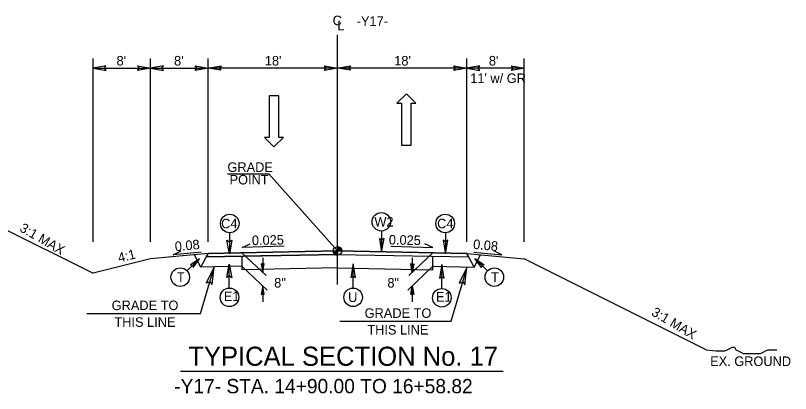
# Model space of a CAD drawing. Extents: x 2320980 to 2456309, y 595047 to 606177.
# Drawn here: x 2456201 to 2456308.8, y 595786.4 to 595839 of the extents above; entities that cross this region are included whole.
import ezdxf

# ---------------------------------------------------------------- set-up
doc = ezdxf.new("R2010")
doc.units = 0
for name, color, linetype in [('Old_Level_1', 7, 'Continuous'), ('Old_Level_11', 7, 'Continuous'), ('Old_Level_2', 7, 'Continuous'), ('Old_Level_20', 7, 'Continuous'), ('Old_Level_21', 7, 'Continuous'), ('Old_Level_3', 7, 'Continuous'), ('Prop Dimension', 7, 'Continuous'), ('Prop Dimension Text', 7, 'Continuous'), ('Prop Lane Arrow CELL', 7, 'Continuous'), ('Prop Terminator CELL', 7, 'Continuous'), ('Typical Grade Point Symbol CELL', 7, 'Continuous'), ('Typical ID Circle CELL', 7, 'Continuous'), ('Typical Pavement Slope CELL', 7, 'Continuous'), ('Typical Pavement Slope Information CELL', 7, 'Continuous'), ('Typical Slope Point Local CELL', 7, 'Continuous'), ('Typical Terminator CELL', 7, 'Continuous')]:
    doc.layers.add(name, color=color, linetype=linetype)

msp = doc.modelspace()

# ---------------------------------------------------------------- linework, layer by layer
at = {"layer": 'Old_Level_1'}
for p, q in [((2456230.5, 595816.96), (2456236.26, 595816.96)), ((2456245.81, 595806.23), (2456236.26, 595816.96)), ((2456227.81, 595805.87), (2456219.81, 595805.12)), ((2456263.81, 595805.87), (2456271.81, 595805.12)), ((2456232.54, 595803.61), (2456232.54, 595805.49)), ((2456259.09, 595803.62), (2456259.09, 595805.49)), ((2456232.54, 595804.09), (2456226.82, 595803.97)), ((2456245.81, 595803.88), (2456232.54, 595803.61)), ((2456245.81, 595803.88), (2456259.09, 595803.62)), ((2456259.09, 595804.09), (2456264.81, 595803.97))]:
    msp.add_line(p, q, dxfattribs=at)
at = {"layer": 'Old_Level_11'}
for points in [[(2456228.36, 595801.55), (2456228.64, 595803.96), (2456227.56, 595801.77), (2456228.05, 595801.94)], [(2456263.55, 595801.51), (2456263.83, 595803.93), (2456262.75, 595801.74), (2456263.24, 595801.91)]]:
    msp.add_lwpolyline(points, close=True, dxfattribs=at)
at = {"layer": 'Old_Level_21'}
for p, q in [((2456211.81, 595807.52), (2456211.81, 595833.02)), ((2456219.81, 595807.52), (2456219.81, 595833.02)), ((2456227.81, 595807.52), (2456227.81, 595833.02)), ((2456263.81, 595807.52), (2456263.81, 595833.02)), ((2456271.81, 595807.52), (2456271.81, 595833.02)), ((2456211.81, 595831.69), (2456219.81, 595831.69)), ((2456219.81, 595831.69), (2456227.81, 595831.69)), ((2456245.81, 595831.69), (2456227.81, 595831.69)), ((2456263.81, 595831.69), (2456245.81, 595831.69)), ((2456271.81, 595831.69), (2456263.81, 595831.69)), ((2456226.76, 595797.52), (2456228.65, 595803.99)), ((2456261.65, 595796.45), (2456263.84, 595803.96)), ((2456210.95, 595797.52), (2456226.76, 595797.52)), ((2456246.14, 595796.45), (2456261.65, 595796.45))]:
    msp.add_line(p, q, dxfattribs=at)
at = {"layer": 'Old_Level_3'}
for p, q in [((2456245.81, 595805.75), (2456227.81, 595805.39)), ((2456223.96, 595789.51), (2456268.88, 595789.51))]:
    msp.add_line(p, q, dxfattribs=at)
at = {"layer": 'Prop Dimension'}
for p, q in [((2456232.53, 595805.97), (2456235.91, 595802.79)), ((2456259.1, 595805.97), (2456255.72, 595802.79)), ((2456235.41, 595805.26), (2456235.41, 595803.26)), ((2456256.22, 595805.26), (2456256.22, 595803.26)), ((2456232.53, 595804.09), (2456236.03, 595800.79)), ((2456259.1, 595804.09), (2456255.6, 595800.79)), ((2456235.41, 595801.38), (2456235.41, 595799.13)), ((2456256.22, 595801.38), (2456256.22, 595799.13))]:
    msp.add_line(p, q, dxfattribs=at)
at = {"layer": 'Prop Dimension Text'}
for p, q in [((2456245.81, 595820.05), (2456245.81, 595836.31)), ((2456245.81, 595801.54), (2456245.81, 595820.05)), ((2456224.88, 595803.47), (2456226.64, 595805.15)), ((2456266.69, 595803.47), (2456264.93, 595805.16))]:
    msp.add_line(p, q, dxfattribs=at)
for points in [[(2456238.39, 595806.88), (2456232.54, 595806.72), (2456233.67, 595807.21)], [(2456253.24, 595806.88), (2456259.09, 595806.72), (2456257.96, 595807.21)], [(2456226.85, 595806.05), (2456222.96, 595805.67), (2456224.06, 595806.24)], [(2456264.78, 595806.05), (2456268.67, 595805.67), (2456267.57, 595806.24)]]:
    msp.add_lwpolyline(points, dxfattribs=at)
for centre in [(2456230.83, 595810.05), (2456251.91, 595810.29), (2456260.8, 595810.05), (2456223.94, 595802.58), (2456267.63, 595802.58), (2456230.79, 595799.77), (2456247.99, 595799.78), (2456260.33, 595799.71)]:
    msp.add_circle(centre, 1.29, dxfattribs=at)
at = {"layer": 'Prop Lane Arrow CELL'}
for p, q in [((2456236.3, 595827.84), (2456236.3, 595822.02)), ((2456237.67, 595827.84), (2456236.3, 595827.84)), ((2456237.67, 595822.02), (2456237.67, 595827.84)), ((2456255.42, 595828.1), (2456254.09, 595826.79)), ((2456256.71, 595826.79), (2456255.42, 595828.1)), ((2456254.09, 595826.79), (2456254.71, 595826.79)), ((2456254.71, 595826.79), (2456254.71, 595820.97)), ((2456256.09, 595820.97), (2456256.09, 595826.79)), ((2456256.09, 595826.79), (2456256.71, 595826.79)), ((2456236.3, 595822.02), (2456235.67, 595822.02)), ((2456235.67, 595822.02), (2456236.96, 595820.71)), ((2456236.96, 595820.71), (2456238.29, 595822.02)), ((2456238.29, 595822.02), (2456237.67, 595822.02)), ((2456254.71, 595820.97), (2456256.09, 595820.97))]:
    msp.add_line(p, q, dxfattribs=at)
at = {"layer": 'Prop Terminator CELL'}
for points in [[(2456235.2, 595804.45), (2456235.41, 595803.26), (2456235.62, 595804.46), (2456235.41, 595804.31)], [(2456256.43, 595804.45), (2456256.22, 595803.26), (2456256.01, 595804.46), (2456256.22, 595804.31)], [(2456235.61, 595800.18), (2456235.41, 595801.38), (2456235.19, 595800.18), (2456235.41, 595800.33)], [(2456256.02, 595800.18), (2456256.22, 595801.38), (2456256.44, 595800.18), (2456256.22, 595800.33)]]:
    msp.add_lwpolyline(points, close=True, dxfattribs=at)
at = {"layer": 'Typical Grade Point Symbol CELL'}
for p, q in [((2456245.81, 595806.23), (2456245.81, 595806.83)), ((2456245.22, 595806.23), (2456245.81, 595806.23)), ((2456246.41, 595806.23), (2456245.81, 595806.23)), ((2456245.81, 595805.64), (2456245.81, 595806.23)), ((2456245.81, 595806.23), (2456245.81, 595805.64))]:
    msp.add_line(p, q, dxfattribs=at)
for points in [[(2456245.82, 595806.83), (2456245.82, 595806.83), (2456245.82, 595806.23)], [(2456245.83, 595806.83), (2456245.83, 595806.23)], [(2456245.84, 595806.83), (2456245.84, 595806.23)], [(2456245.85, 595806.83), (2456245.85, 595806.23)], [(2456245.87, 595806.83), (2456245.87, 595806.23)], [(2456245.88, 595806.83), (2456245.88, 595806.23)], [(2456245.89, 595806.82), (2456245.89, 595806.23)], [(2456245.9, 595806.82), (2456245.9, 595806.23)], [(2456245.91, 595806.82), (2456245.91, 595806.23)], [(2456245.93, 595806.82), (2456245.93, 595806.23)], [(2456245.94, 595806.82), (2456245.94, 595806.23)], [(2456245.95, 595806.81), (2456245.95, 595806.23)], [(2456245.96, 595806.81), (2456245.96, 595806.23)], [(2456245.97, 595806.81), (2456245.97, 595806.23)], [(2456245.99, 595806.8), (2456245.99, 595806.23)], [(2456246, 595806.8), (2456246, 595806.23)], [(2456246.01, 595806.8), (2456246.01, 595806.23)], [(2456246.02, 595806.79), (2456246.02, 595806.23)], [(2456246.03, 595806.79), (2456246.03, 595806.23)], [(2456246.04, 595806.78), (2456246.04, 595806.23)], [(2456246.06, 595806.78), (2456246.06, 595806.23)], [(2456246.07, 595806.77), (2456246.07, 595806.23)], [(2456246.08, 595806.77), (2456246.08, 595806.23)], [(2456246.09, 595806.76), (2456246.09, 595806.23)], [(2456246.1, 595806.75), (2456246.1, 595806.23)], [(2456245.22, 595806.23), (2456245.22, 595806.17)], [(2456245.23, 595806.23), (2456245.23, 595806.1)], [(2456245.24, 595806.23), (2456245.24, 595806.06)], [(2456245.26, 595806.23), (2456245.26, 595806.02)], [(2456245.27, 595806.23), (2456245.27, 595805.99)], [(2456245.28, 595806.23), (2456245.28, 595805.97)], [(2456245.29, 595806.23), (2456245.29, 595805.95)], [(2456245.3, 595806.23), (2456245.3, 595805.92)], [(2456245.32, 595806.23), (2456245.32, 595805.91)], [(2456245.33, 595806.23), (2456245.33, 595805.89)], [(2456245.34, 595806.23), (2456245.34, 595805.87)], [(2456245.35, 595806.23), (2456245.35, 595805.86)], [(2456245.36, 595806.23), (2456245.36, 595805.84)], [(2456245.38, 595806.23), (2456245.38, 595805.83)], [(2456245.39, 595806.23), (2456245.39, 595805.82)], [(2456245.4, 595806.23), (2456245.4, 595805.81)], [(2456245.41, 595806.23), (2456245.41, 595805.79)], [(2456245.42, 595806.23), (2456245.42, 595805.78)], [(2456245.44, 595806.23), (2456245.44, 595805.77)], [(2456245.45, 595806.23), (2456245.45, 595805.76)], [(2456245.46, 595806.23), (2456245.46, 595805.75)], [(2456245.47, 595806.23), (2456245.47, 595805.75)], [(2456245.48, 595806.23), (2456245.48, 595805.74)], [(2456245.49, 595806.23), (2456245.49, 595805.73)], [(2456245.51, 595806.23), (2456245.51, 595805.72)], [(2456245.52, 595806.23), (2456245.52, 595805.72)], [(2456245.53, 595806.23), (2456245.53, 595805.71)], [(2456245.54, 595806.23), (2456245.54, 595805.7)], [(2456245.55, 595806.23), (2456245.55, 595805.7)], [(2456245.57, 595806.23), (2456245.57, 595805.69)], [(2456245.58, 595806.23), (2456245.58, 595805.69)], [(2456245.59, 595806.23), (2456245.59, 595805.68)], [(2456245.6, 595806.23), (2456245.6, 595805.68)], [(2456245.61, 595806.23), (2456245.61, 595805.67)], [(2456245.63, 595806.23), (2456245.63, 595805.67)], [(2456245.64, 595806.23), (2456245.64, 595805.66)], [(2456245.65, 595806.23), (2456245.65, 595805.66)], [(2456245.66, 595806.23), (2456245.66, 595805.66)], [(2456245.67, 595806.23), (2456245.67, 595805.66)], [(2456245.69, 595806.23), (2456245.69, 595805.65)], [(2456245.7, 595806.23), (2456245.7, 595805.65)], [(2456245.71, 595806.23), (2456245.71, 595805.65)], [(2456245.72, 595806.23), (2456245.72, 595805.65)], [(2456245.73, 595806.23), (2456245.73, 595805.64)], [(2456245.74, 595806.23), (2456245.74, 595805.64)], [(2456245.76, 595806.23), (2456245.76, 595805.64)], [(2456245.77, 595806.23), (2456245.77, 595805.64)], [(2456245.78, 595806.23), (2456245.78, 595805.64)], [(2456245.79, 595806.23), (2456245.79, 595805.64)], [(2456245.8, 595806.23), (2456245.8, 595805.64), (2456245.8, 595805.64)], [(2456246.12, 595806.75), (2456246.12, 595806.23)], [(2456246.13, 595806.74), (2456246.13, 595806.23)], [(2456246.14, 595806.73), (2456246.14, 595806.23)], [(2456246.15, 595806.72), (2456246.15, 595806.23)], [(2456246.16, 595806.71), (2456246.16, 595806.23)], [(2456246.18, 595806.71), (2456246.18, 595806.23)], [(2456246.19, 595806.7), (2456246.19, 595806.23)], [(2456246.2, 595806.69), (2456246.2, 595806.23)], [(2456246.21, 595806.68), (2456246.21, 595806.23)], [(2456246.22, 595806.66), (2456246.22, 595806.23)], [(2456246.24, 595806.65), (2456246.24, 595806.23)], [(2456246.25, 595806.64), (2456246.25, 595806.23)], [(2456246.26, 595806.63), (2456246.26, 595806.23)], [(2456246.27, 595806.61), (2456246.27, 595806.23)], [(2456246.28, 595806.6), (2456246.28, 595806.23)], [(2456246.3, 595806.58), (2456246.3, 595806.23)], [(2456246.31, 595806.57), (2456246.31, 595806.23)], [(2456246.32, 595806.55), (2456246.32, 595806.23)], [(2456246.33, 595806.53), (2456246.33, 595806.23)], [(2456246.34, 595806.51), (2456246.34, 595806.23)], [(2456246.35, 595806.48), (2456246.35, 595806.23)], [(2456246.37, 595806.45), (2456246.37, 595806.23)], [(2456246.38, 595806.42), (2456246.38, 595806.23)], [(2456246.39, 595806.38), (2456246.39, 595806.23)], [(2456246.4, 595806.32), (2456246.4, 595806.23)]]:
    msp.add_lwpolyline(points, dxfattribs=at)
msp.add_circle((2456245.81, 595806.23), 0.595, dxfattribs=at)
for start, end in [(359.9905, 89.9905), (179.9905, 269.9905)]:
    msp.add_arc((2456245.81, 595806.23), 0.595, start, end, dxfattribs=at)
at = {"layer": 'Typical ID Circle CELL'}
for p, q in [((2456251.96, 595809.02), (2456251.96, 595806.08)), ((2456230.78, 595808.78), (2456230.78, 595805.84)), ((2456260.85, 595808.78), (2456260.85, 595805.84)), ((2456230.76, 595801.07), (2456230.76, 595804.41)), ((2456248.01, 595801.08), (2456248.01, 595804.42)), ((2456260.35, 595801.01), (2456260.35, 595804.35))]:
    msp.add_line(p, q, dxfattribs=at)
at = {"layer": 'Typical Pavement Slope CELL'}
for p, q in [((2456226.82, 595803.97), (2456225.93, 595805.69)), ((2456226.82, 595803.97), (2456227.81, 595805.87)), ((2456227.81, 595805.87), (2456227.56, 595805.4)), ((2456227.56, 595805.39), (2456227.81, 595805.87)), ((2456227.56, 595805.4), (2456245.81, 595805.75)), ((2456245.81, 595805.75), (2456227.56, 595805.39)), ((2456245.81, 595806.23), (2456227.81, 595805.87)), ((2456245.81, 595806.23), (2456227.81, 595805.87)), ((2456227.81, 595805.87), (2456245.81, 595806.23)), ((2456245.81, 595806.23), (2456263.81, 595805.87)), ((2456245.81, 595805.75), (2456245.81, 595806.23)), ((2456263.81, 595805.87), (2456245.81, 595806.23)), ((2456245.81, 595806.23), (2456245.81, 595805.75)), ((2456245.81, 595806.23), (2456245.81, 595805.75)), ((2456245.81, 595805.75), (2456264.07, 595805.39)), ((2456264.07, 595805.39), (2456263.81, 595805.87)), ((2456264.81, 595803.97), (2456263.82, 595805.87)), ((2456264.81, 595803.97), (2456265.7, 595805.69)), ((2456237.07, 595805.58), (2456227.52, 595805.38))]:
    msp.add_line(p, q, dxfattribs=at)
at = {"layer": 'Typical Slope Point Local CELL'}
for p, q in [((2456196.28, 595810.89), (2456211.81, 595803.12)), ((2456219.81, 595805.12), (2456211.81, 595803.12)), ((2456297.1, 595792.48), (2456271.81, 595805.12))]:
    msp.add_line(p, q, dxfattribs=at)
msp.add_lwpolyline([(2456297.1, 595792.48), (2456298.48, 595792.31), (2456298.82, 595792.31), (2456299.34, 595792.31), (2456299.69, 595792.31), (2456300.03, 595792.48), (2456300.38, 595792.65), (2456300.72, 595792.83), (2456301.07, 595792.83), (2456301.24, 595792.48), (2456301.58, 595792.31), (2456301.93, 595792.14), (2456302.27, 595791.96), (2456302.62, 595791.96), (2456302.96, 595791.96), (2456303.31, 595791.96), (2456303.65, 595791.96), (2456304, 595791.96), (2456304.34, 595791.96), (2456304.69, 595791.96), (2456305.03, 595792.14), (2456305.38, 595792.31), (2456305.72, 595792.48), (2456306.24, 595792.48), (2456306.59, 595792.48), (2456306.93, 595792.48)], dxfattribs=at)
at = {"layer": 'Typical Terminator CELL'}
for points in [[(2456213.61, 595832), (2456211.81, 595831.69), (2456213.62, 595831.37), (2456213.39, 595831.69)], [(2456218.02, 595832), (2456219.81, 595831.69), (2456218.01, 595831.37), (2456218.24, 595831.69)], [(2456221.61, 595832), (2456219.81, 595831.69), (2456221.62, 595831.37), (2456221.39, 595831.69)], [(2456226.02, 595832), (2456227.81, 595831.69), (2456226.01, 595831.37), (2456226.24, 595831.69)], [(2456229.61, 595831.38), (2456227.81, 595831.69), (2456229.62, 595832.01), (2456229.39, 595831.69)], [(2456244.02, 595832), (2456245.81, 595831.69), (2456244.01, 595831.37), (2456244.24, 595831.69)], [(2456247.61, 595831.38), (2456245.81, 595831.69), (2456247.62, 595832.01), (2456247.39, 595831.69)], [(2456262.02, 595832), (2456263.81, 595831.69), (2456262.01, 595831.37), (2456262.24, 595831.69)], [(2456265.61, 595832), (2456263.81, 595831.69), (2456265.62, 595831.37), (2456265.39, 595831.69)], [(2456270.02, 595832), (2456271.81, 595831.69), (2456270.01, 595831.37), (2456270.24, 595831.69)], [(2456251.64, 595807.97), (2456251.96, 595806.08), (2456252.3, 595807.98), (2456251.96, 595807.74)], [(2456231.11, 595807.73), (2456230.78, 595805.84), (2456230.44, 595807.74), (2456230.78, 595807.5)], [(2456260.52, 595807.73), (2456260.85, 595805.84), (2456261.19, 595807.74), (2456260.85, 595807.5)], [(2456225.73, 595803.93), (2456226.64, 595805.15), (2456225.36, 595804.31), (2456225.69, 595804.25)], [(2456265.84, 595803.94), (2456264.93, 595805.16), (2456266.2, 595804.31), (2456265.88, 595804.25)], [(2456230.44, 595802.52), (2456230.76, 595804.41), (2456231.1, 595802.5), (2456230.76, 595802.75)], [(2456248.34, 595802.52), (2456248.01, 595804.42), (2456247.68, 595802.51), (2456248.01, 595802.76)], [(2456260.68, 595802.45), (2456260.35, 595804.35), (2456260.02, 595802.44), (2456260.35, 595802.68)]]:
    msp.add_lwpolyline(points, close=True, dxfattribs=at)

# ---------------------------------------------------------------- texts
at = {"layer": 'Old_Level_1'}
for s, p in [('GRADE', (2456230.51, 595817.23)), ('POINT', (2456230.8, 595815.49))]:
    msp.add_text(s, height=1.33, dxfattribs=at).set_placement(p)
msp.add_text('EX. GROUND', height=1.33, rotation=359.9103, dxfattribs=at).set_placement((2456297.66, 595790.22))
at = {"layer": 'Old_Level_2'}
for s, height, p in [('TYPICAL SECTION No. 17', 2.66, (2456225.06, 595790.24)), ('-Y17- STA. 14+90.00 TO 16+58.82', 1.995, (2456223.1, 595786.41))]:
    msp.add_text(s, height=height, dxfattribs=at).set_placement(p)
at = {"layer": 'Old_Level_20'}
for s, p in [('C4', (2456229.63, 595809.38)), ('T', (2456223.48, 595801.91)), ('E1', (2456230, 595799.25))]:
    msp.add_text(s, height=1.33, rotation=0, dxfattribs=at).set_placement(p)
for s, p in [('W2', (2456250.95, 595809.63)), ('C4', (2456259.68, 595809.38)), ('T', (2456267.19, 595801.92)), ('U', (2456247.3, 595799.12)), ('E1', (2456259.52, 595799.18))]:
    msp.add_text(s, height=1.33, dxfattribs=at).set_placement(p)
at = {"layer": 'Old_Level_21'}
for s, rotation, p in [('C', 0.0002, (2456245.14, 595837.66)), ('L', 0.0002, (2456245.8, 595836.95)), ('3:1 MAX', 329.8879, (2456201.48, 595809.05)), ('0.025', 1.1456, (2456233.92, 595807.04)), ('0.025', 358.8544, (2456252.95, 595807.13)), ('0.08', 354.6583, (2456264.64, 595806.53)), ('0.08', 5.3417, (2456223.25, 595806.18)), ('3:1 MAX', 329.3616, (2456289.38, 595797.35))]:
    msp.add_text(s, height=1.33, rotation=rotation, dxfattribs=at).set_placement(p)
for s, p in [('-Y17-', (2456248.49, 595837.56)), ("8'", (2456215.08, 595832.05)), ("8'", (2456223.08, 595832.05)), ("18'", (2456235.71, 595832.05)), ("18'", (2456253.71, 595832.05)), ("8'", (2456266.88, 595832.05)), ("11' w/ GR", (2456264.28, 595829.61)), ('GRADE TO', (2456214.4, 595797.99)), ('GRADE TO', (2456249.59, 595796.91)), ('THIS LINE', (2456214.78, 595795.66)), ('THIS LINE', (2456249.97, 595794.59))]:
    msp.add_text(s, height=1.33, dxfattribs=at).set_placement(p)
at = {"layer": 'Typical Pavement Slope Information CELL'}
msp.add_text('8"', height=1.33, rotation=0, dxfattribs=at).set_placement((2456237.01, 595801.13))
msp.add_text('8"', height=1.33, dxfattribs=at).set_placement((2456252.76, 595801.13))
at = {"layer": 'Typical Slope Point Local CELL'}
msp.add_text('4:1', height=1.33, rotation=14.0362, dxfattribs=at).set_placement((2456215.45, 595804.6))

doc.saveas('drawing.dxf')
